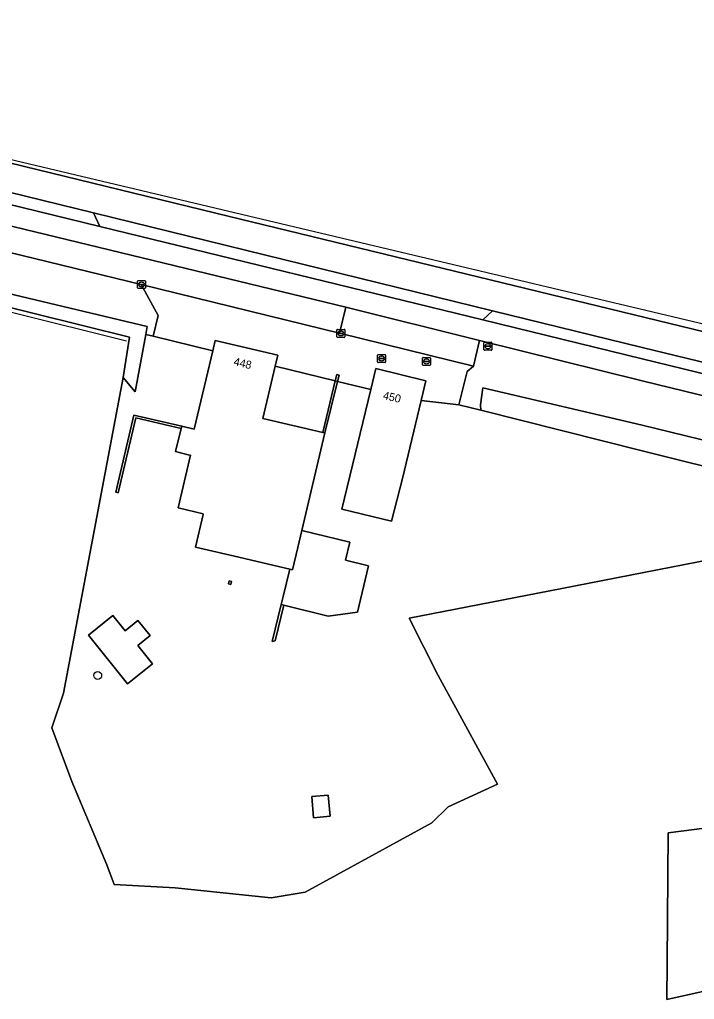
# Model space of a CAD drawing. Extents: x 163859 to 164644, y 379566 to 382155.
# Drawn here: x 164422.2 to 164506.5, y 382032.9 to 382155.2 of the extents above; entities that cross this region are included whole.
import ezdxf

# ---------------------------------------------------------------- set-up
doc = ezdxf.new("R2010")
doc.units = 0
for name, color, linetype in [('IMGEO_Boom', 7, 'Continuous'), ('IMGEO_Brandkraan', 7, 'Continuous'), ('IMGEO_Erf', 7, 'Continuous'), ('IMGEO_Fietspad_gesloten', 7, 'Continuous'), ('IMGEO_Grasland_agrarisch', 7, 'Continuous'), ('IMGEO_Groenvoorziening', 7, 'Continuous'), ('IMGEO_Hek', 7, 'Continuous'), ('IMGEO_Kolk', 7, 'Continuous'), ('IMGEO_Muur', 7, 'Continuous'), ('IMGEO_Pand', 7, 'Continuous'), ('IMGEO_Pand_nummerreeks', 7, 'Continuous'), ('IMGEO_Rijbaan_regionaal_gesloten', 7, 'Continuous'), ('IMGEO_Rioolput', 7, 'Continuous'), ('IMGEO_Verkeerseiland_groen', 7, 'Continuous'), ('IMGEO_Voetpad_open', 7, 'Continuous'), ('IMGEO_Waterloop', 7, 'Continuous')]:
    doc.layers.add(name, color=color, linetype=linetype)

msp = doc.modelspace()

# ---------------------------------------------------------------- linework, layer by layer
at = {"layer": 'IMGEO_Boom'}
msp.add_circle((164431.95, 382073.32), 0.489, dxfattribs=at)
at = {"layer": 'IMGEO_Brandkraan'}
for p, q in [((164466.92, 382112.48), (164466.92, 382113.33)), ((164467, 382113.41), (164467.85, 382113.41)), ((164467.18, 382112.9), (164467.18, 382112.91)), ((164467.62, 382112.86), (164467.22, 382112.86)), ((164467.23, 382112.95), (164467.62, 382112.95)), ((164467.41, 382113.19), (164467.44, 382113.19)), ((164467.43, 382112.63), (164467.41, 382112.63)), ((164467.67, 382112.91), (164467.67, 382112.9)), ((164467.92, 382113.33), (164467.92, 382112.48)), ((164467.85, 382112.41), (164467, 382112.41))]:
    msp.add_line(p, q, dxfattribs=at)
for points in [[(164466.92, 382112.48), (164466.92, 382113.33)], [(164467, 382113.41), (164467.85, 382113.41)], [(164467.92, 382113.33), (164467.92, 382112.48)], [(164467.85, 382112.41), (164467, 382112.41)]]:
    msp.add_lwpolyline(points, dxfattribs=at)
for centre, radius, start, end in [((164467, 382113.33), 0.0765, 91.552, 178.448), ((164467, 382113.33), 0.0765, 91.552, 178.448), ((164467.22, 382112.91), 0.0403, 85.8775, 175.7526), ((164467.22, 382112.9), 0.0366, 178.938, 274.7102), ((164467.63, 382112.91), 0.0386, 1.7309, 96.639), ((164467.62, 382112.91), 0.043, 264.8664, 352.4533), ((164467.85, 382113.33), 0.0765, 1.552, 88.448), ((164467.85, 382113.33), 0.0765, 1.552, 88.448), ((164467, 382112.48), 0.0765, 181.552, 268.448), ((164467, 382112.48), 0.0765, 181.552, 268.448), ((164467.85, 382112.48), 0.0765, 271.552, 358.448), ((164467.85, 382112.48), 0.0765, 271.552, 358.448)]:
    msp.add_arc(centre, radius, start, end, dxfattribs=at)
for centre, major_axis, ratio, start_param, end_param in [((164467.41, 382112.91), (-0.387, 0.002), 0.722429, 4.712389, 7.853982), ((164467.43, 382112.91), (-0.39, 0.002), 0.717154, 1.570796, 4.712389)]:
    msp.add_ellipse(centre, major_axis=major_axis, ratio=ratio, start_param=start_param, end_param=end_param, dxfattribs=at)
at = {"layer": 'IMGEO_Erf'}
for points in [[(164513.2, 382098.08), (164500, 382101.39), (164479.82, 382106.45), (164477.07, 382107.14), (164472.37, 382107.67), (164470.02, 382097.9), (164468.64, 382092.61), (164462.45, 382094.09), (164466.08, 382109.03), (164461.92, 382110.05), (164460.32, 382103.62), (164457.45, 382091.42), (164463.45, 382089.97), (164462.91, 382087.72), (164465.79, 382087.03), (164464.39, 382081.22), (164460.74, 382080.74), (164455.21, 382082.11), (164454.11, 382077.65), (164453.76, 382077.58), (164454.89, 382082.19), (164455.13, 382083.17), (164455.96, 382086.58), (164449.04, 382088.21), (164444.15, 382089.35), (164445.11, 382093.44), (164445.13, 382093.51), (164441.98, 382094.25), (164443.53, 382100.82), (164443.27, 382100.89), (164441.68, 382101.29), (164442.38, 382104.17), (164436.7, 382105.49), (164434.5, 382096.14), (164434.21, 382096.2), (164436.48, 382105.85), (164442.45, 382104.46), (164444.02, 382104.07), (164446.32, 382113.87), (164438.86, 382115.68), (164437.95, 382115.91), (164436.64, 382108.73), (164435.11, 382110.54), (164427.68, 382071.12), (164426.21, 382066.78), (164428.71, 382060.09), (164433.1, 382049.68), (164434.01, 382047.23), (164441.62, 382046.78), (164453.63, 382045.54), (164457.89, 382046.24), (164473.68, 382054.91), (164475.75, 382056.93), (164481.92, 382059.76), (164474.51, 382073.3), (164470.87, 382080.47), (164489.95, 382084.16), (164508.72, 382087.84)], [(164509.38, 382054.47), (164503.23, 382053.66), (164503.12, 382037.46), (164503.08, 382032.86), (164523.11, 382037.28)]]:
    msp.add_lwpolyline(points, dxfattribs=at)
for points in [[(164461.63, 382110.12), (164454.12, 382111.96), (164452.58, 382105.43), (164460.06, 382103.68)], [(164448.58, 382084.68), (164448.28, 382084.76), (164448.38, 382085.13), (164448.68, 382085.05)], [(164438.51, 382078.3), (164436.95, 382077.05), (164438.79, 382074.76), (164435.68, 382072.26), (164430.8, 382078.35), (164433.85, 382080.8), (164435.36, 382078.91), (164436.98, 382080.2)], [(164461.01, 382055.74), (164458.93, 382055.55), (164458.69, 382058.19), (164460.76, 382058.38)]]:
    msp.add_lwpolyline(points, close=True, dxfattribs=at)
at = {"layer": 'IMGEO_Fietspad_gesloten'}
for points in [[(164351.79, 382149.02), (164352.26, 382146.27), (164358.29, 382144.8), (164362.68, 382143.73), (164380.09, 382139.4), (164383.9, 382138.46), (164391.87, 382136.53), (164462.95, 382119.3), (164479.66, 382115.15), (164500, 382110.11), (164547.27, 382098.59), (164553.37, 382097.11), (164566.02, 382094.03)], [(164566.61, 382096.62), (164500, 382112.87), (164480.06, 382117.73), (164432.23, 382129.4), (164397.28, 382137.92), (164390.72, 382139.52), (164384.51, 382141.04), (164380.7, 382141.97), (164360.68, 382146.85), (164351.79, 382149.02)]]:
    msp.add_lwpolyline(points, dxfattribs=at)
at = {"layer": 'IMGEO_Grasland_agrarisch'}
for points in [[(164508.72, 382087.84), (164489.95, 382084.16), (164470.87, 382080.47), (164474.51, 382073.3), (164481.92, 382059.76), (164475.75, 382056.93), (164473.68, 382054.91), (164457.89, 382046.24), (164453.63, 382045.54), (164441.62, 382046.78), (164434.01, 382047.23), (164433.1, 382049.68), (164428.71, 382060.09), (164426.21, 382066.78), (164427.68, 382071.12), (164435.11, 382110.54), (164435.91, 382115.59), (164393.78, 382126.01)], [(164523.11, 382037.28), (164503.08, 382032.86), (164503.12, 382037.46), (164503.23, 382053.66), (164509.38, 382054.47)]]:
    msp.add_lwpolyline(points, dxfattribs=at)
at = {"layer": 'IMGEO_Groenvoorziening'}
for points in [[(164397.34, 382131.91), (164396.25, 382126.85), (164438.14, 382116.92), (164437.95, 382115.91), (164438.86, 382115.68), (164439.49, 382118.28), (164437.36, 382122.16)], [(164547.27, 382098.59), (164500, 382110.11), (164479.66, 382115.15), (164478.89, 382111.96), (164478.13, 382111.27), (164477.07, 382107.14), (164479.82, 382106.45), (164479.77, 382107.13), (164480.07, 382109.25), (164500, 382104.57), (164537.87, 382095.33), (164545.32, 382093.66), (164546.64, 382093.3), (164547.48, 382094.92)]]:
    msp.add_lwpolyline(points, close=True, dxfattribs=at)
msp.add_lwpolyline([(164595.08, 382091.12), (164593.39, 382091.53), (164576.43, 382095.76), (164500, 382114.28), (164481.27, 382118.87), (164480.06, 382117.73), (164500, 382112.87), (164566.61, 382096.62)], dxfattribs=at)
at = {"layer": 'IMGEO_Hek'}
msp.add_lwpolyline([(164392.9, 382125.72), (164435.55, 382115.13)], dxfattribs=at)
at = {"layer": 'IMGEO_Kolk'}
for p, q in [((164436.92, 382121.72), (164436.92, 382122.58)), ((164436.99, 382122.65), (164437.85, 382122.65)), ((164437.41, 382122.43), (164437.43, 382122.43)), ((164437.92, 382122.58), (164437.92, 382121.72)), ((164437.85, 382121.65), (164436.99, 382121.65)), ((164437.18, 382122.14), (164437.18, 382122.16)), ((164437.22, 382122.19), (164437.62, 382122.19)), ((164437.62, 382122.11), (164437.22, 382122.11)), ((164437.43, 382121.87), (164437.4, 382121.87)), ((164437.66, 382122.16), (164437.66, 382122.14)), ((164461.83, 382115.62), (164461.83, 382116.47)), ((164461.91, 382116.54), (164462.76, 382116.54)), ((164462.32, 382116.32), (164462.35, 382116.32)), ((164462.83, 382116.47), (164462.83, 382115.62)), ((164462.76, 382115.54), (164461.91, 382115.54)), ((164462.09, 382116.04), (164462.09, 382116.05)), ((164462.53, 382116), (164462.13, 382116)), ((164462.14, 382116.09), (164462.53, 382116.09)), ((164462.34, 382115.76), (164462.32, 382115.76)), ((164462.58, 382116.05), (164462.58, 382116.04))]:
    msp.add_line(p, q, dxfattribs=at)
for points in [[(164436.92, 382121.72), (164436.92, 382122.58)], [(164436.99, 382122.65), (164437.85, 382122.65)], [(164437.92, 382122.58), (164437.92, 382121.72)], [(164437.85, 382121.65), (164436.99, 382121.65)], [(164461.83, 382115.62), (164461.83, 382116.47)], [(164461.91, 382116.54), (164462.76, 382116.54)], [(164462.83, 382116.47), (164462.83, 382115.62)], [(164462.76, 382115.54), (164461.91, 382115.54)]]:
    msp.add_lwpolyline(points, dxfattribs=at)
for centre, radius, start, end in [((164437, 382122.57), 0.0765, 91.552, 178.448), ((164437, 382122.57), 0.0765, 91.552, 178.448), ((164437.84, 382122.57), 0.0765, 1.552, 88.448), ((164437.84, 382122.57), 0.0765, 1.552, 88.448), ((164437, 382121.73), 0.0765, 181.552, 268.448), ((164437, 382121.73), 0.0765, 181.552, 268.448), ((164437.22, 382122.15), 0.0403, 85.8775, 175.7526), ((164437.21, 382122.14), 0.0366, 178.938, 274.7102), ((164437.62, 382122.15), 0.0386, 1.7309, 96.639), ((164437.62, 382122.15), 0.043, 264.8664, 352.4533), ((164437.84, 382121.73), 0.0765, 271.552, 358.448), ((164437.84, 382121.73), 0.0765, 271.552, 358.448), ((164461.91, 382116.47), 0.0765, 91.552, 178.448), ((164461.91, 382116.47), 0.0765, 91.552, 178.448), ((164462.76, 382116.47), 0.0765, 1.552, 88.448), ((164462.76, 382116.47), 0.0765, 1.552, 88.448), ((164461.91, 382115.62), 0.0765, 181.552, 268.448), ((164461.91, 382115.62), 0.0765, 181.552, 268.448), ((164462.13, 382116.05), 0.0403, 85.8775, 175.7526), ((164462.13, 382116.04), 0.0366, 178.938, 274.7102), ((164462.54, 382116.05), 0.0386, 1.7309, 96.639), ((164462.53, 382116.04), 0.043, 264.8664, 352.4533), ((164462.76, 382115.62), 0.0765, 271.552, 358.448), ((164462.76, 382115.62), 0.0765, 271.552, 358.448)]:
    msp.add_arc(centre, radius, start, end, dxfattribs=at)
for centre, major_axis, ratio, start_param, end_param in [((164437.41, 382122.15), (-0.387, 0.002), 0.722429, 4.712389, 7.853982), ((164437.43, 382122.15), (-0.39, 0.002), 0.717154, 1.570796, 4.712389), ((164462.32, 382116.04), (-0.387, 0.002), 0.722429, 4.712389, 7.853982), ((164462.34, 382116.04), (-0.39, 0.002), 0.717154, 1.570796, 4.712389)]:
    msp.add_ellipse(centre, major_axis=major_axis, ratio=ratio, start_param=start_param, end_param=end_param, dxfattribs=at)
at = {"layer": 'IMGEO_Muur'}
for points in [[(164461.63, 382110.12), (164460.06, 382103.68), (164460.32, 382103.62), (164461.92, 382110.05)], [(164461.92, 382110.05), (164462.12, 382110.84), (164461.82, 382110.92), (164461.63, 382110.12)], [(164436.48, 382105.85), (164434.21, 382096.2), (164434.5, 382096.14), (164436.7, 382105.49), (164442.38, 382104.17), (164442.45, 382104.46)], [(164454.89, 382082.19), (164453.76, 382077.58), (164454.11, 382077.65), (164455.21, 382082.11)]]:
    msp.add_lwpolyline(points, close=True, dxfattribs=at)
at = {"layer": 'IMGEO_Pand'}
for points in [[(164460.32, 382103.62), (164460.06, 382103.68), (164452.58, 382105.43), (164454.12, 382111.96), (164454.44, 382113.34), (164446.63, 382115.17), (164446.32, 382113.87), (164444.02, 382104.07), (164442.45, 382104.46), (164442.38, 382104.17), (164441.68, 382101.29), (164443.27, 382100.89), (164443.53, 382100.82), (164441.98, 382094.25), (164445.13, 382093.51), (164445.11, 382093.44), (164444.15, 382089.35), (164449.04, 382088.21), (164455.96, 382086.58), (164456.29, 382086.5), (164456.96, 382089.32), (164457.45, 382091.42)], [(164472.37, 382107.67), (164472.96, 382110.12), (164466.71, 382111.64), (164466.08, 382109.03), (164462.45, 382094.09), (164468.64, 382092.61), (164470.02, 382097.9)], [(164465.79, 382087.03), (164462.91, 382087.72), (164463.45, 382089.97), (164457.45, 382091.42), (164456.96, 382089.32), (164456.29, 382086.5), (164455.96, 382086.58), (164455.13, 382083.17), (164454.89, 382082.19), (164455.21, 382082.11), (164460.74, 382080.74), (164464.39, 382081.22)], [(164448.68, 382085.05), (164448.38, 382085.13), (164448.28, 382084.76), (164448.58, 382084.68)], [(164438.51, 382078.3), (164436.98, 382080.2), (164435.36, 382078.91), (164433.85, 382080.8), (164430.8, 382078.35), (164435.68, 382072.26), (164438.79, 382074.76), (164436.95, 382077.05)], [(164458.69, 382058.19), (164458.93, 382055.55), (164461.01, 382055.74), (164460.76, 382058.38)]]:
    msp.add_lwpolyline(points, close=True, dxfattribs=at)
at = {"layer": 'IMGEO_Rijbaan_regionaal_gesloten'}
for points in [[(164350.74, 382155.24), (164350.86, 382154.51), (164352.35, 382154.14), (164422.81, 382136.88), (164448.24, 382130.7), (164525.74, 382111.86), (164595.63, 382094.81), (164595.86, 382096.24), (164391.82, 382144.66), (164350.74, 382155.24)], [(164595.63, 382094.81), (164525.74, 382111.86), (164448.24, 382130.7), (164422.81, 382136.88), (164352.35, 382154.14), (164350.86, 382154.51), (164351.52, 382150.65), (164362.07, 382148.07), (164380.56, 382143.54), (164385.35, 382142.37), (164389.85, 382141.27), (164399.24, 382138.97), (164431.4, 382131.09), (164481.27, 382118.87), (164500, 382114.28), (164576.43, 382095.76), (164593.39, 382091.53), (164595.08, 382091.12), (164595.07, 382091.22), (164595.07, 382091.33), (164595.63, 382094.81)]]:
    msp.add_lwpolyline(points, dxfattribs=at)
at = {"layer": 'IMGEO_Rioolput'}
for p, q in [((164480.2, 382114.01), (164480.2, 382114.87)), ((164480.28, 382114.94), (164481.13, 382114.94)), ((164481.13, 382113.94), (164480.28, 382113.94)), ((164480.46, 382114.43), (164480.46, 382114.45)), ((164480.5, 382114.48), (164480.9, 382114.48)), ((164480.9, 382114.4), (164480.5, 382114.4)), ((164480.69, 382114.72), (164480.71, 382114.72)), ((164480.71, 382114.16), (164480.69, 382114.16)), ((164480.94, 382114.45), (164480.94, 382114.43)), ((164481.2, 382114.87), (164481.2, 382114.01)), ((164472.53, 382112.11), (164472.53, 382112.96)), ((164472.6, 382113.04), (164473.46, 382113.04)), ((164472.79, 382112.53), (164472.79, 382112.54)), ((164472.83, 382112.58), (164473.23, 382112.58)), ((164473.02, 382112.82), (164473.04, 382112.82)), ((164473.27, 382112.54), (164473.27, 382112.53)), ((164473.53, 382112.96), (164473.53, 382112.11)), ((164473.46, 382112.04), (164472.6, 382112.04)), ((164473.23, 382112.49), (164472.83, 382112.49)), ((164473.04, 382112.26), (164473.02, 382112.26))]:
    msp.add_line(p, q, dxfattribs=at)
for points in [[(164480.2, 382114.01), (164480.2, 382114.87)], [(164480.28, 382114.94), (164481.13, 382114.94)], [(164481.13, 382113.94), (164480.28, 382113.94)], [(164481.2, 382114.87), (164481.2, 382114.01)], [(164472.53, 382112.11), (164472.53, 382112.96)], [(164472.6, 382113.04), (164473.46, 382113.04)], [(164473.53, 382112.96), (164473.53, 382112.11)], [(164473.46, 382112.04), (164472.6, 382112.04)]]:
    msp.add_lwpolyline(points, dxfattribs=at)
for centre, radius, start, end in [((164480.28, 382114.87), 0.0765, 91.552, 178.448), ((164480.28, 382114.87), 0.0765, 91.552, 178.448), ((164480.28, 382114.02), 0.0765, 181.552, 268.448), ((164480.28, 382114.02), 0.0765, 181.552, 268.448), ((164480.5, 382114.44), 0.0403, 85.8775, 175.7526), ((164480.5, 382114.43), 0.0366, 178.938, 274.7102), ((164480.91, 382114.45), 0.0386, 1.7309, 96.639), ((164480.9, 382114.44), 0.043, 264.8664, 352.4533), ((164481.13, 382114.87), 0.0765, 1.552, 88.448), ((164481.13, 382114.87), 0.0765, 1.552, 88.448), ((164481.13, 382114.02), 0.0765, 271.552, 358.448), ((164481.13, 382114.02), 0.0765, 271.552, 358.448), ((164472.61, 382112.96), 0.0765, 91.552, 178.448), ((164472.61, 382112.96), 0.0765, 91.552, 178.448), ((164472.83, 382112.54), 0.0403, 85.8775, 175.7526), ((164472.83, 382112.53), 0.0366, 178.938, 274.7102), ((164473.23, 382112.54), 0.0386, 1.7309, 96.639), ((164473.23, 382112.54), 0.043, 264.8664, 352.4533), ((164473.45, 382112.96), 0.0765, 1.552, 88.448), ((164473.45, 382112.96), 0.0765, 1.552, 88.448), ((164472.61, 382112.11), 0.0765, 181.552, 268.448), ((164472.61, 382112.11), 0.0765, 181.552, 268.448), ((164473.45, 382112.11), 0.0765, 271.552, 358.448), ((164473.45, 382112.11), 0.0765, 271.552, 358.448)]:
    msp.add_arc(centre, radius, start, end, dxfattribs=at)
for centre, major_axis, ratio, start_param, end_param in [((164480.69, 382114.44), (-0.387, 0.002), 0.722429, 4.712389, 7.853982), ((164480.71, 382114.44), (-0.39, 0.002), 0.717154, 1.570796, 4.712389), ((164473.02, 382112.54), (-0.387, 0.002), 0.722429, 4.712389, 7.853982), ((164473.04, 382112.54), (-0.39, 0.002), 0.717154, 1.570796, 4.712389)]:
    msp.add_ellipse(centre, major_axis=major_axis, ratio=ratio, start_param=start_param, end_param=end_param, dxfattribs=at)
at = {"layer": 'IMGEO_Verkeerseiland_groen'}
msp.add_lwpolyline([(164399.24, 382138.97), (164397.28, 382137.92), (164432.23, 382129.4), (164431.4, 382131.09)], close=True, dxfattribs=at)
at = {"layer": 'IMGEO_Voetpad_open'}
for points in [[(164391.87, 382136.53), (164383.9, 382138.46), (164380.09, 382139.4), (164362.68, 382143.73), (164361.9, 382140.47), (164362.86, 382140.28), (164386.16, 382134.63), (164391.61, 382133.31), (164393.95, 382132.74), (164397.34, 382131.91), (164437.36, 382122.16), (164462.15, 382116.09), (164462.95, 382119.3)], [(164432.23, 382129.4), (164480.06, 382117.73), (164481.27, 382118.87), (164431.4, 382131.09)], [(164462.15, 382116.09), (164437.36, 382122.16), (164439.49, 382118.28), (164438.86, 382115.68), (164446.32, 382113.87), (164446.63, 382115.17), (164454.44, 382113.34), (164454.12, 382111.96), (164461.63, 382110.12), (164461.82, 382110.92), (164462.12, 382110.84), (164461.92, 382110.05), (164466.08, 382109.03), (164466.71, 382111.64), (164472.96, 382110.12), (164472.37, 382107.67), (164477.07, 382107.14), (164478.13, 382111.27), (164478.89, 382111.96)], [(164479.66, 382115.15), (164462.95, 382119.3), (164462.15, 382116.09), (164478.89, 382111.96)]]:
    msp.add_lwpolyline(points, close=True, dxfattribs=at)
at = {"layer": 'IMGEO_Waterloop'}
for points in [[(164396.25, 382126.85), (164395.22, 382127.09), (164394.18, 382127.34), (164393.98, 382126.66), (164393.78, 382126.01), (164435.91, 382115.59), (164435.11, 382110.54), (164436.64, 382108.73), (164437.95, 382115.91), (164438.14, 382116.92)], [(164500, 382104.57), (164480.07, 382109.25), (164479.77, 382107.13), (164479.82, 382106.45), (164500, 382101.39), (164513.2, 382098.08), (164522.31, 382095.81), (164544.39, 382090.34), (164545.3, 382092.48), (164545.44, 382093.5), (164545.32, 382093.66), (164537.87, 382095.33)]]:
    msp.add_lwpolyline(points, close=True, dxfattribs=at)

# ---------------------------------------------------------------- texts
at = {"layer": 'IMGEO_Pand_nummerreeks'}
for s, rotation, p in [('448', 346.7704, (164448.87, 382112.08)), ('450', 346.7735, (164467.53, 382107.86))]:
    msp.add_text(s, height=1, rotation=rotation, dxfattribs=at).set_placement(p)

doc.saveas('drawing.dxf')
